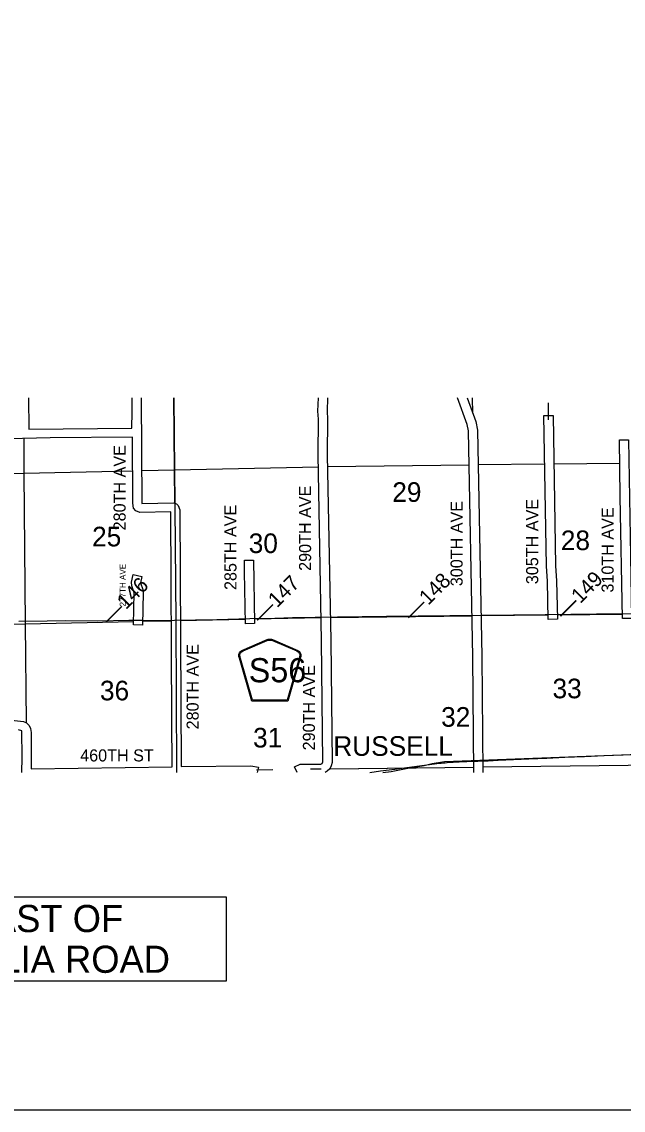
# Model space of a CAD drawing. Extents: x 10133 to 81668, y 5524 to 11018.
# Drawn here: x 19016 to 19515, y 7924 to 8826 of the extents above; entities that cross this region are included whole.
import ezdxf

# ---------------------------------------------------------------- set-up
doc = ezdxf.new("R2010")
doc.units = 0
for name, color, linetype in [('Default', 7, 'Continuous'), ('DisCLMLSUR', 7, 'Continuous'), ('DsnShtRevisedText', 7, 'Continuous'), ('Level 3', 7, 'Continuous'), ('trf_Signal_(Temp)_Layout', 7, 'Continuous')]:
    doc.layers.add(name, color=color, linetype=linetype)

msp = doc.modelspace()

# ---------------------------------------------------------------- linework, layer by layer
at = {"layer": 'Default'}
for points in [[(19022.02, 8514.04), (19022.08, 8488.02), (19107.55, 8489.05)], [(19107.55, 8489.05), (19107.91, 8502.55), (19107.81, 8514.04)], [(19115.15, 8514.04), (19115.72, 8426.69), (19142.2, 8427.07), (19144.5, 8426.3), (19146.02, 8425.04), (19147.27, 8421.3), (19148.31, 8208.59), (19206.11, 8209.37), (19212.34, 8208.23), (19211.36, 8203.88)], [(19142.23, 8514.04), (19142.98, 8454.56)], [(19143.19, 8427.71), (19142.98, 8454.56), (19142.23, 8514.04)], [(19142.23, 8514.04), (19142.98, 8454.56), (19143.95, 8329.59), (19144.62, 8204.85), (19144.63, 8203.88)], [(19244.5, 8203.88), (19242.22, 8208.44), (19246.99, 8210.57), (19264.06, 8210.55), (19265.24, 8211.14), (19265.82, 8212.47), (19264.72, 8312.96), (19261.76, 8466.82), (19262.07, 8496.34), (19261.7, 8503.08), (19262.04, 8514.04)], [(19269.54, 8514.04), (19269.2, 8503), (19269.57, 8496.52), (19269.26, 8466.9), (19272.22, 8313.05), (19273.31, 8212.02), (19272.71, 8209.21), (19271.42, 8206.86), (19269.39, 8204.83), (19267.71, 8203.88)], [(19390.81, 8203.88), (19390.03, 8299.65), (19386.24, 8486.83), (19385.24, 8492.06), (19377.32, 8514.04)], [(19385.26, 8514.04), (19392.34, 8494.45), (19393.73, 8487.21), (19397.53, 8299.77), (19398.32, 8203.88)], [(19389.52, 8514.04), (19389.78, 8501.49)], [(19452.59, 8495.82), (19452.61, 8509.91)], [(19452.47, 8330.46), (19451.7, 8362.25), (19450.96, 8374.71), (19448.85, 8499.57), (19456.34, 8499.56), (19458.46, 8374.86), (19459.2, 8362.46), (19459.96, 8330.73), (19452.47, 8330.46)], [(18997.55, 8248.16), (19017.72, 8246.02), (19020.26, 8244.96), (19022.49, 8242.71), (19023.7, 8240.14), (19024.14, 8236.82), (19024.07, 8206.92), (19140.81, 8208.52), (19140.65, 8248.06), (19139.77, 8419.65), (19114.11, 8419.24), (19110.75, 8420.44), (19108.86, 8422.59), (19108.22, 8426.72), (19108.04, 8481.55), (19039.8, 8480.87), (18959.72, 8479.16)], [(19018.07, 8480.49), (19018.07, 8451.6)], [(19511.94, 8432.43), (19511.35, 8479.28), (19518.85, 8479.35), (19520.64, 8383.09), (19521.44, 8331.3), (19513.95, 8331.18), (19511.94, 8432.43)], [(19142.98, 8454.56), (19262.08, 8457.05)], [(19269.58, 8457.18), (19386.88, 8458.7)], [(19394.38, 8458.78), (19449.41, 8459.3)], [(19456.9, 8459.38), (19511.61, 8459.89)], [(18959.78, 8450.47), (19018.07, 8451.6)], [(19018.07, 8451.6), (19108.22, 8453.74)], [(19018.07, 8451.6), (19019.13, 8326.78)], [(19115.69, 8453.91), (19142.98, 8454.56)], [(19142.98, 8454.56), (19143.2, 8426.85)], [(19201.6, 8327.03), (19200.71, 8370.01), (19200.86, 8379.7), (19208.36, 8379.58), (19209.09, 8327.28), (19201.6, 8327.03)], [(19116.31, 8325.81), (19108.82, 8326.04), (19109.43, 8352.51), (19107.48, 8358.31), (19107.1, 8361.29), (19108.51, 8367.81), (19115.8, 8366.05), (19114.63, 8360.86), (19116.62, 8355.25), (19116.93, 8352.79), (19116.31, 8325.81)], [(19147.65, 8329.66), (19201.49, 8330.76)], [(19208.98, 8330.91), (19264.38, 8332.03)], [(19271.88, 8332.16), (19389.39, 8333.63)], [(19396.89, 8333.72), (19452.33, 8334.29)], [(19459.83, 8334.37), (19513.89, 8334.93)], [(18975.68, 8326.43), (19019.13, 8326.78)], [(19019.13, 8326.78), (19108.89, 8328.8)], [(19019.13, 8326.78), (19019.91, 8245.11)], [(19116.39, 8328.97), (19140.18, 8329.5)], [(19016.53, 8203.88), (19016.64, 8216.27), (19016.38, 8238.34), (19013.68, 8239.04)], [(19304.76, 8203.88), (19313.6, 8205.06), (19325.28, 8206.62), (19329.26, 8207.15), (19333.23, 8207.68), (19343.62, 8209.06), (19354, 8210.44), (19356.03, 8210.72), (19358.07, 8211.01), (19360, 8211.22), (19361.93, 8211.42), (19363.76, 8211.61), (19365.59, 8211.79), (19366.95, 8211.88), (19368.3, 8211.96), (19368.81, 8211.98), (19373.68, 8212.24), (19378.54, 8212.49), (19385.1, 8212.76), (19391.65, 8213.03), (19392.85, 8213.08), (19394.05, 8213.13), (19402.51, 8213.51), (19410.98, 8213.89), (19423.64, 8214.44), (19436.3, 8215), (19451.2, 8215.68), (19466.11, 8216.36), (19482.35, 8217.03), (19498.58, 8217.71), (19514.35, 8218.39), (19530.12, 8219.07)], [(19315.5, 8203.88), (19322.2, 8204.51), (19337.58, 8207.52), (19349.61, 8209.53), (19356.32, 8211.13), (19366.37, 8212.74), (19542.37, 8219.58), (19558.56, 8215.09), (19572.78, 8210.99), (19588.78, 8205.7), (19596.28, 8204.35), (19598, 8203.88)], [(19315.5, 8203.88), (19322.2, 8204.51), (19337.58, 8207.52), (19349.61, 8209.53), (19356.32, 8211.13), (19366.37, 8212.74), (19421.12, 8214.86)], [(19210.86, 8205.9), (19224.32, 8206.11)], [(19255.61, 8206.67), (19259.22, 8206.79), (19264.42, 8206.8)], [(19271.42, 8206.85), (19390.62, 8208.31)], [(19271.7, 8206.85), (19390.6, 8208.31)], [(19398.11, 8208.4), (19518.6, 8209.89), (19638.82, 8211.09)], [(19398.11, 8208.4), (19518.6, 8209.89)]]:
    msp.add_lwpolyline(points, dxfattribs=at)
for points in [[(19206.85, 8262.95), (19196.6, 8298.32), (19196.12, 8299.96), (19196.03, 8300.7), (19196.03, 8301.67), (19196.56, 8302.96), (19197.47, 8304.02), (19198.66, 8304.86), (19219.57, 8313.9), (19220.51, 8314.11), (19221.82, 8314.22), (19223.12, 8314.11), (19224.06, 8313.9), (19244.97, 8304.86), (19246.17, 8304.02), (19247.07, 8302.96), (19247.61, 8301.67), (19247.61, 8300.7), (19247.51, 8299.96), (19247.03, 8298.32), (19236.79, 8262.95)], [(19207.58, 8263.75), (19197.61, 8298.15), (19197.15, 8299.73), (19197.06, 8300.44), (19197.06, 8301.38), (19197.57, 8302.62), (19198.44, 8303.63), (19199.59, 8304.43), (19219.66, 8313.12), (19220.57, 8313.31), (19221.82, 8313.42), (19223.07, 8313.31), (19223.97, 8313.12), (19244.04, 8304.43), (19245.19, 8303.63), (19246.06, 8302.62), (19246.57, 8301.38), (19246.57, 8300.44), (19246.49, 8299.73), (19246.02, 8298.15), (19236.05, 8263.75)]]:
    msp.add_lwpolyline(points, close=True, dxfattribs=at)
at = {"layer": 'DsnShtRevisedText'}
msp.add_lwpolyline([(19549.05, 8335.31), (19492.29, 8334.87), (19449.73, 8334.32), (19318.47, 8332.96), (19277.81, 8332.28), (19240.53, 8331.83), (19225.93, 8331.33), (19205.22, 8330.9), (19178.03, 8330.31), (19125.13, 8329.26), (19116.1, 8329.6), (19105.12, 8329.77), (19079.23, 8329.23), (19052.63, 8329.42), (19037.37, 8329.05), (19013.82, 8328.77)], dxfattribs=at)
at = {"layer": 'Level 3'}
msp.add_lwpolyline([(17332.52, 9944.02), (20467.53, 9944.02), (20467.53, 7924.02), (17332.52, 7924.02)], close=True, dxfattribs=at)
at = {"layer": 'trf_Signal_(Temp)_Layout'}
msp.add_lwpolyline([(18732.97, 8031.33), (19185.79, 8031.33), (19185.79, 8100.58), (18732.97, 8100.58)], close=True, dxfattribs=at)

# ---------------------------------------------------------------- texts
at = {"layer": 'Default'}
for s, height, rotation, p in [('280TH AVE', 10, 90, (19102.36, 8404.32)), ('290TH AVE', 10, 90, (19255.99, 8370.74)), ('29', 16.25, 0.01345, (19323.23, 8427.91)), ('305TH AVE', 10, 90, (19444.09, 8359.75)), ('285TH AVE', 10, 90, (19194.2, 8354.91)), ('300TH AVE', 10, 90, (19381.51, 8358.08)), ('310TH AVE', 10, 90, (19506.55, 8352.77)), ('25', 16.25, 0.01197, (19074.6, 8391.04)), ('28', 16.25, 0.01428, (19462.83, 8387.94)), ('30', 16.25, 0.01273, (19204.33, 8385.52)), ('277TH AVE', 5, 90, (19102.43, 8341.29)), ('‒‒147', 12.5, 45, (19214.63, 8326.55)), ('‒‒148', 12.5, 45, (19339.8, 8328.62)), ('‒‒149', 12.5, 45, (19465.76, 8329.94)), ('‒‒146', 12.5, 45, (19089.45, 8324.99)), ('280TH AVE', 10, 90, (19162.86, 8239.49)), ('290TH AVE', 10, 90, (19259.18, 8222.08)), ('36', 16.25, 0.01202, (19081.1, 8263.51)), ('33', 16.25, 0.01425, (19455.94, 8265.23)), ('32', 16.25, 0.01351, (19363.7, 8241.67)), ('31', 16.25, 0.01277, (19207.93, 8224.47)), ('RUSSELL', 16.25, 0.01342, (19274.37, 8217.55))]:
    msp.add_text(s, height=height, rotation=rotation, dxfattribs=at).set_placement(p)
for s, height, p in [('S56', 20, (19204.37, 8278.49)), ('460TH ST', 10, (19064.75, 8212.92))]:
    msp.add_text(s, height=height, dxfattribs=at).set_placement(p)
at = {"layer": 'DisCLMLSUR'}
for s, p in [('PLACE SIGN EAST OF ', (18782.66, 8071.58)), ('BUSINESS 34 / ABLIA ROAD', (18739.47, 8037.83))]:
    msp.add_text(s, height=22.5, dxfattribs=at).set_placement(p)

doc.saveas('drawing.dxf')
